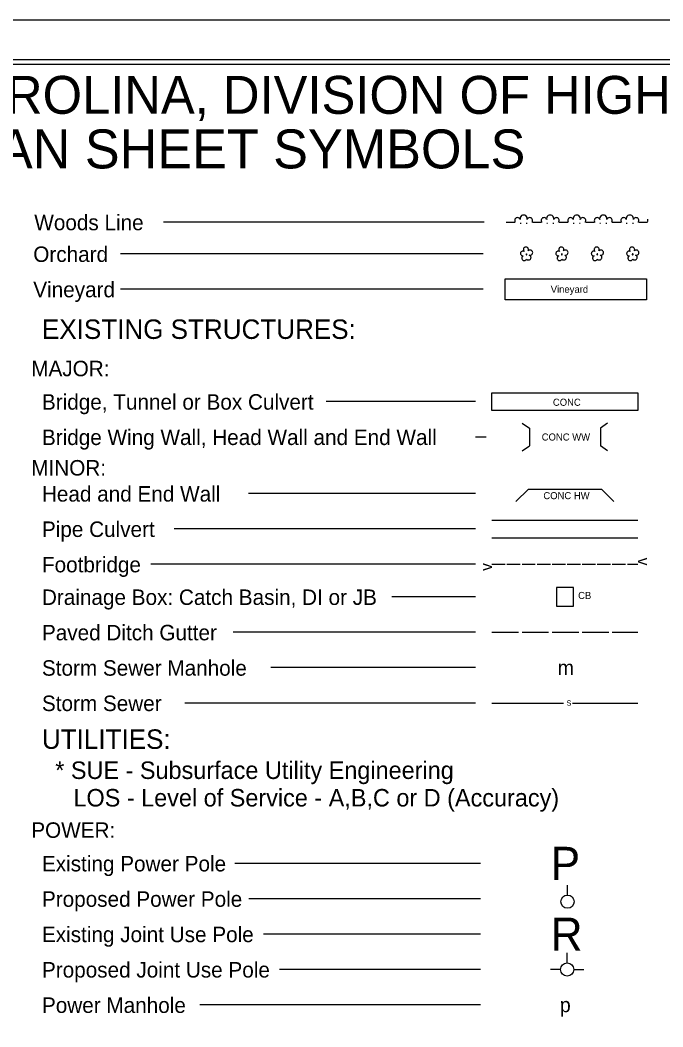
# Model space of a CAD drawing. Extents: x 1523758 to 1525442, y 311788 to 312888.
# Drawn here: x 1524681 to 1525044, y 312319 to 312888 of the extents above; entities that cross this region are included whole.
import ezdxf

# ---------------------------------------------------------------- set-up
doc = ezdxf.new("R2010")
doc.units = 0
for name, color, linetype in [('Sheet Cutting Line CELL', 7, 'Continuous'), ('Sheet Plot Border Inside CELL', 7, 'Continuous'), ('Sheet Plot Border Outside CELL', 7, 'Continuous'), ('Sheet Symbology CELL', 7, 'Continuous')]:
    doc.layers.add(name, color=color, linetype=linetype)

msp = doc.modelspace()

# ---------------------------------------------------------------- linework, layer by layer
at = {"layer": 'Sheet Cutting Line CELL'}
msp.add_line((1525442.07, 312888.39), (1523758.07, 312888.39), dxfattribs=at)
msp.add_line((1525442.07, 312888.39), (1523758.07, 312888.39), dxfattribs=at)
at = {"layer": 'Sheet Plot Border Inside CELL'}
msp.add_lwpolyline([(1523771.07, 311810.84), (1525437.57, 311810.84), (1525437.57, 312865.94), (1523771.07, 312865.94)], close=True, dxfattribs=at)
at = {"layer": 'Sheet Plot Border Outside CELL'}
msp.add_lwpolyline([(1523758.07, 311788.39), (1525442.07, 311788.39), (1525442.07, 312888.39), (1523758.07, 312888.39)], close=True, dxfattribs=at)
at = {"layer": 'Sheet Symbology CELL'}
for p, q in [((1524943.33, 312774.12), (1524762.21, 312774.12)), ((1524955.72, 312774.12), (1524960.72, 312774.12)), ((1524970.72, 312774.12), (1524975.72, 312774.12)), ((1524985.72, 312774.12), (1524990.72, 312774.12)), ((1525000.72, 312774.12), (1525005.72, 312774.12)), ((1525015.72, 312774.12), (1525020.72, 312774.12)), ((1525030.72, 312774.12), (1525035.72, 312774.12)), ((1524963.67, 312773.62), (1524964.17, 312773.62)), ((1524967.17, 312773.62), (1524967.67, 312773.62)), ((1524978.67, 312773.62), (1524979.17, 312773.62)), ((1524982.17, 312773.62), (1524982.67, 312773.62)), ((1524993.67, 312773.62), (1524994.17, 312773.62)), ((1524997.17, 312773.62), (1524997.67, 312773.62)), ((1525008.67, 312773.62), (1525009.17, 312773.62)), ((1525012.17, 312773.62), (1525012.67, 312773.62)), ((1525023.67, 312773.62), (1525024.17, 312773.62)), ((1525027.17, 312773.62), (1525027.67, 312773.62)), ((1524942.76, 312756.2), (1524737.83, 312756.2)), ((1524942.76, 312736.2), (1524737.83, 312736.2)), ((1524938.45, 312672.69), (1524854.02, 312672.69)), ((1524964.9, 312660.55), (1524969, 312657.69)), ((1525013.1, 312660.55), (1525009, 312657.69)), ((1524969, 312657.69), (1524969, 312647.69)), ((1525009, 312657.69), (1525009, 312647.69)), ((1524938.45, 312652.69), (1524944.44, 312652.69)), ((1524964.9, 312644.83), (1524969, 312647.69)), ((1525013.1, 312644.83), (1525009, 312647.69)), ((1524938.45, 312620.7), (1524810.15, 312620.7)), ((1524961.3, 312616.12), (1524968.37, 312623.2)), ((1524968.37, 312623.2), (1525009.62, 312623.2)), ((1525009.62, 312623.2), (1525016.7, 312616.12)), ((1524947.75, 312605.7), (1525030.25, 312605.7)), ((1524938.45, 312600.7), (1524768.26, 312600.7)), ((1524947.75, 312595.7), (1525030.25, 312595.7)), ((1524938.45, 312580.7), (1524754.97, 312580.7)), ((1524947.75, 312580.7), (1524955.25, 312580.7)), ((1524956.25, 312580.7), (1524963.75, 312580.7)), ((1524964.75, 312580.7), (1524972.25, 312580.7)), ((1524973.25, 312580.7), (1524980.75, 312580.7)), ((1524981.75, 312580.7), (1524989.25, 312580.7)), ((1524990.25, 312580.7), (1524997.75, 312580.7)), ((1524998.75, 312580.7), (1525006.25, 312580.7)), ((1525007.25, 312580.7), (1525014.75, 312580.7)), ((1525015.75, 312580.7), (1525023.25, 312580.7)), ((1525024.25, 312580.7), (1525030.25, 312580.7)), ((1524938.45, 312562.26), (1524891.25, 312562.26)), ((1524938.45, 312542.26), (1524801.5, 312542.26)), ((1524947.75, 312542.26), (1524962.75, 312542.26)), ((1524964.75, 312542.26), (1524979.75, 312542.26)), ((1524981.75, 312542.26), (1524996.75, 312542.26)), ((1524998.75, 312542.26), (1525013.75, 312542.26)), ((1525015.75, 312542.26), (1525030.25, 312542.26)), ((1524938.45, 312522.26), (1524822.77, 312522.26)), ((1524938.45, 312502.26), (1524774.25, 312502.26)), ((1524947.75, 312502.26), (1524988.27, 312502.26)), ((1524993.27, 312502.26), (1525030.25, 312502.26)), ((1524941.24, 312411.58), (1524802.54, 312411.58)), ((1524990.46, 312393.69), (1524990.46, 312399.32)), ((1524941.24, 312391.58), (1524810.32, 312391.58)), ((1524941.24, 312371.58), (1524818.72, 312371.58)), ((1524990.25, 312355.34), (1524990.25, 312360.97)), ((1524941.24, 312351.58), (1524827.72, 312351.58)), ((1524986.5, 312351.59), (1524980.87, 312351.59)), ((1524994, 312351.59), (1524999.62, 312351.59)), ((1524941.24, 312331.58), (1524782.74, 312331.58))]:
    msp.add_line(p, q, dxfattribs=at)
for points in [[(1525425.07, 312863.39), (1523925.07, 312863.39), (1523925.07, 311814.41), (1525425.07, 311814.41)], [(1524984.19, 312556.95), (1524993.8, 312556.95), (1524993.8, 312567.59), (1524984.19, 312567.59)]]:
    msp.add_lwpolyline(points, close=True, dxfattribs=at)
for points in [[(1524968.21, 312757.95), (1524968.36, 312758.25), (1524968.41, 312758.55), (1524968.36, 312758.85), (1524968.31, 312759.15), (1524968.16, 312759.4), (1524968.01, 312759.65), (1524967.76, 312759.85), (1524967.51, 312760), (1524967.16, 312760.1), (1524966.91, 312760.1), (1524966.61, 312760.05), (1524966.31, 312759.95), (1524966.06, 312759.8), (1524965.81, 312759.6), (1524965.66, 312759.3), (1524965.56, 312759.05), (1524965.51, 312758.75), (1524965.51, 312758.45), (1524965.56, 312758.15), (1524965.71, 312757.9), (1524965.91, 312757.6), (1524965.66, 312757.75), (1524965.36, 312757.8), (1524965.06, 312757.8), (1524964.81, 312757.7), (1524964.56, 312757.6), (1524964.31, 312757.4), (1524964.11, 312757.2), (1524963.96, 312756.95), (1524963.91, 312756.7), (1524963.86, 312756.35), (1524963.91, 312756.1), (1524964.01, 312755.85), (1524964.21, 312755.6), (1524964.36, 312755.4), (1524964.61, 312755.25), (1524964.91, 312755.1), (1524965.16, 312755.05), (1524965.46, 312755.05), (1524965.21, 312754.95), (1524964.96, 312754.75), (1524964.81, 312754.55), (1524964.71, 312754.25), (1524964.61, 312753.95), (1524964.61, 312753.7), (1524964.66, 312753.4), (1524964.81, 312753.15), (1524964.96, 312752.9), (1524965.16, 312752.7), (1524965.41, 312752.55), (1524965.66, 312752.45), (1524965.96, 312752.45), (1524966.26, 312752.45), (1524966.51, 312752.5), (1524966.76, 312752.7), (1524967.01, 312752.85), (1524967.26, 312753.3)], [(1524967.26, 312753.3), (1524967.86, 312752.95), (1524968.16, 312752.85), (1524968.46, 312752.8), (1524968.76, 312752.85), (1524969.01, 312752.95), (1524969.26, 312753.1), (1524969.51, 312753.3), (1524969.66, 312753.55), (1524969.76, 312753.8), (1524969.86, 312754.1), (1524969.81, 312754.4), (1524969.76, 312754.7), (1524969.56, 312755), (1524969.41, 312755.2), (1524969.16, 312755.35), (1524968.86, 312755.5), (1524969.16, 312755.45), (1524969.51, 312755.45), (1524969.76, 312755.55), (1524970.06, 312755.7), (1524970.31, 312755.85), (1524970.51, 312756.1), (1524970.66, 312756.4), (1524970.71, 312756.7), (1524970.76, 312757), (1524970.71, 312757.3), (1524970.61, 312757.6), (1524970.41, 312757.85), (1524970.16, 312758.1), (1524969.91, 312758.25), (1524969.61, 312758.35), (1524969.31, 312758.4), (1524969.01, 312758.4), (1524968.71, 312758.3), (1524968.46, 312758.15), (1524968.21, 312757.95)], [(1524988.21, 312757.95), (1524988.36, 312758.25), (1524988.41, 312758.55), (1524988.36, 312758.85), (1524988.31, 312759.15), (1524988.16, 312759.4), (1524988.01, 312759.65), (1524987.76, 312759.85), (1524987.51, 312760), (1524987.16, 312760.1), (1524986.91, 312760.1), (1524986.61, 312760.05), (1524986.31, 312759.95), (1524986.06, 312759.8), (1524985.81, 312759.6), (1524985.66, 312759.3), (1524985.56, 312759.05), (1524985.51, 312758.75), (1524985.51, 312758.45), (1524985.56, 312758.15), (1524985.71, 312757.9), (1524985.91, 312757.6), (1524985.66, 312757.75), (1524985.36, 312757.8), (1524985.06, 312757.8), (1524984.81, 312757.7), (1524984.56, 312757.6), (1524984.31, 312757.4), (1524984.11, 312757.2), (1524983.96, 312756.95), (1524983.91, 312756.7), (1524983.86, 312756.35), (1524983.91, 312756.1), (1524984.01, 312755.85), (1524984.21, 312755.6), (1524984.36, 312755.4), (1524984.61, 312755.25), (1524984.91, 312755.1), (1524985.16, 312755.05), (1524985.46, 312755.05), (1524985.21, 312754.95), (1524984.96, 312754.75), (1524984.81, 312754.55), (1524984.71, 312754.25), (1524984.61, 312753.95), (1524984.61, 312753.7), (1524984.66, 312753.4), (1524984.81, 312753.15), (1524984.96, 312752.9), (1524985.16, 312752.7), (1524985.41, 312752.55), (1524985.66, 312752.45), (1524985.96, 312752.45), (1524986.26, 312752.45), (1524986.51, 312752.5), (1524986.76, 312752.7), (1524987.01, 312752.85), (1524987.26, 312753.3)], [(1524987.26, 312753.3), (1524987.86, 312752.95), (1524988.16, 312752.85), (1524988.46, 312752.8), (1524988.76, 312752.85), (1524989.01, 312752.95), (1524989.26, 312753.1), (1524989.51, 312753.3), (1524989.66, 312753.55), (1524989.76, 312753.8), (1524989.86, 312754.1), (1524989.81, 312754.4), (1524989.76, 312754.7), (1524989.56, 312755), (1524989.41, 312755.2), (1524989.16, 312755.35), (1524988.86, 312755.5), (1524989.16, 312755.45), (1524989.51, 312755.45), (1524989.76, 312755.55), (1524990.06, 312755.7), (1524990.31, 312755.85), (1524990.51, 312756.1), (1524990.66, 312756.4), (1524990.71, 312756.7), (1524990.76, 312757), (1524990.71, 312757.3), (1524990.61, 312757.6), (1524990.41, 312757.85), (1524990.16, 312758.1), (1524989.91, 312758.25), (1524989.61, 312758.35), (1524989.31, 312758.4), (1524989.01, 312758.4), (1524988.71, 312758.3), (1524988.46, 312758.15), (1524988.21, 312757.95)], [(1525008.21, 312757.95), (1525008.36, 312758.25), (1525008.41, 312758.55), (1525008.36, 312758.85), (1525008.31, 312759.15), (1525008.16, 312759.4), (1525008.01, 312759.65), (1525007.76, 312759.85), (1525007.51, 312760), (1525007.16, 312760.1), (1525006.91, 312760.1), (1525006.61, 312760.05), (1525006.31, 312759.95), (1525006.06, 312759.8), (1525005.81, 312759.6), (1525005.66, 312759.3), (1525005.56, 312759.05), (1525005.51, 312758.75), (1525005.51, 312758.45), (1525005.56, 312758.15), (1525005.71, 312757.9), (1525005.91, 312757.6), (1525005.66, 312757.75), (1525005.36, 312757.8), (1525005.06, 312757.8), (1525004.81, 312757.7), (1525004.56, 312757.6), (1525004.31, 312757.4), (1525004.11, 312757.2), (1525003.96, 312756.95), (1525003.91, 312756.7), (1525003.86, 312756.35), (1525003.91, 312756.1), (1525004.01, 312755.85), (1525004.21, 312755.6), (1525004.36, 312755.4), (1525004.61, 312755.25), (1525004.91, 312755.1), (1525005.16, 312755.05), (1525005.46, 312755.05), (1525005.21, 312754.95), (1525004.96, 312754.75), (1525004.81, 312754.55), (1525004.71, 312754.25), (1525004.61, 312753.95), (1525004.61, 312753.7), (1525004.66, 312753.4), (1525004.81, 312753.15), (1525004.96, 312752.9), (1525005.16, 312752.7), (1525005.41, 312752.55), (1525005.66, 312752.45), (1525005.96, 312752.45), (1525006.26, 312752.45), (1525006.51, 312752.5), (1525006.76, 312752.7), (1525007.01, 312752.85), (1525007.26, 312753.3)], [(1525007.26, 312753.3), (1525007.86, 312752.95), (1525008.16, 312752.85), (1525008.46, 312752.8), (1525008.76, 312752.85), (1525009.01, 312752.95), (1525009.26, 312753.1), (1525009.51, 312753.3), (1525009.66, 312753.55), (1525009.76, 312753.8), (1525009.86, 312754.1), (1525009.81, 312754.4), (1525009.76, 312754.7), (1525009.56, 312755), (1525009.41, 312755.2), (1525009.16, 312755.35), (1525008.86, 312755.5), (1525009.16, 312755.45), (1525009.51, 312755.45), (1525009.76, 312755.55), (1525010.06, 312755.7), (1525010.31, 312755.85), (1525010.51, 312756.1), (1525010.66, 312756.4), (1525010.71, 312756.7), (1525010.76, 312757), (1525010.71, 312757.3), (1525010.61, 312757.6), (1525010.41, 312757.85), (1525010.16, 312758.1), (1525009.91, 312758.25), (1525009.61, 312758.35), (1525009.31, 312758.4), (1525009.01, 312758.4), (1525008.71, 312758.3), (1525008.46, 312758.15), (1525008.21, 312757.95)], [(1525028.21, 312757.95), (1525028.36, 312758.25), (1525028.41, 312758.55), (1525028.36, 312758.85), (1525028.31, 312759.15), (1525028.16, 312759.4), (1525028.01, 312759.65), (1525027.76, 312759.85), (1525027.51, 312760), (1525027.16, 312760.1), (1525026.91, 312760.1), (1525026.61, 312760.05), (1525026.31, 312759.95), (1525026.06, 312759.8), (1525025.81, 312759.6), (1525025.66, 312759.3), (1525025.56, 312759.05), (1525025.51, 312758.75), (1525025.51, 312758.45), (1525025.56, 312758.15), (1525025.71, 312757.9), (1525025.91, 312757.6), (1525025.66, 312757.75), (1525025.36, 312757.8), (1525025.06, 312757.8), (1525024.81, 312757.7), (1525024.56, 312757.6), (1525024.31, 312757.4), (1525024.11, 312757.2), (1525023.96, 312756.95), (1525023.91, 312756.7), (1525023.86, 312756.35), (1525023.91, 312756.1), (1525024.01, 312755.85), (1525024.21, 312755.6), (1525024.36, 312755.4), (1525024.61, 312755.25), (1525024.91, 312755.1), (1525025.16, 312755.05), (1525025.46, 312755.05), (1525025.21, 312754.95), (1525024.96, 312754.75), (1525024.81, 312754.55), (1525024.71, 312754.25), (1525024.61, 312753.95), (1525024.61, 312753.7), (1525024.66, 312753.4), (1525024.81, 312753.15), (1525024.96, 312752.9), (1525025.16, 312752.7), (1525025.41, 312752.55), (1525025.66, 312752.45), (1525025.96, 312752.45), (1525026.26, 312752.45), (1525026.51, 312752.5), (1525026.76, 312752.7), (1525027.01, 312752.85), (1525027.26, 312753.3)], [(1525027.26, 312753.3), (1525027.86, 312752.95), (1525028.16, 312752.85), (1525028.46, 312752.8), (1525028.76, 312752.85), (1525029.01, 312752.95), (1525029.26, 312753.1), (1525029.51, 312753.3), (1525029.66, 312753.55), (1525029.76, 312753.8), (1525029.86, 312754.1), (1525029.81, 312754.4), (1525029.76, 312754.7), (1525029.56, 312755), (1525029.41, 312755.2), (1525029.16, 312755.35), (1525028.86, 312755.5), (1525029.16, 312755.45), (1525029.51, 312755.45), (1525029.76, 312755.55), (1525030.06, 312755.7), (1525030.31, 312755.85), (1525030.51, 312756.1), (1525030.66, 312756.4), (1525030.71, 312756.7), (1525030.76, 312757), (1525030.71, 312757.3), (1525030.61, 312757.6), (1525030.41, 312757.85), (1525030.16, 312758.1), (1525029.91, 312758.25), (1525029.61, 312758.35), (1525029.31, 312758.4), (1525029.01, 312758.4), (1525028.71, 312758.3), (1525028.46, 312758.15), (1525028.21, 312757.95)], [(1524967.36, 312756.2), (1524967.21, 312756.2), (1524967.11, 312756.15), (1524967.01, 312756.1), (1524967.01, 312755.95), (1524967.01, 312755.85), (1524967.11, 312755.75), (1524967.26, 312755.75), (1524967.36, 312755.75), (1524967.46, 312755.85), (1524967.51, 312756), (1524967.46, 312756.1), (1524967.36, 312756.2)], [(1524987.36, 312756.2), (1524987.21, 312756.2), (1524987.11, 312756.15), (1524987.01, 312756.1), (1524987.01, 312755.95), (1524987.01, 312755.85), (1524987.11, 312755.75), (1524987.26, 312755.75), (1524987.36, 312755.75), (1524987.46, 312755.85), (1524987.51, 312756), (1524987.46, 312756.1), (1524987.36, 312756.2)], [(1525007.36, 312756.2), (1525007.21, 312756.2), (1525007.11, 312756.15), (1525007.01, 312756.1), (1525007.01, 312755.95), (1525007.01, 312755.85), (1525007.11, 312755.75), (1525007.26, 312755.75), (1525007.36, 312755.75), (1525007.46, 312755.85), (1525007.51, 312756), (1525007.46, 312756.1), (1525007.36, 312756.2)], [(1525027.36, 312756.2), (1525027.21, 312756.2), (1525027.11, 312756.15), (1525027.01, 312756.1), (1525027.01, 312755.95), (1525027.01, 312755.85), (1525027.11, 312755.75), (1525027.26, 312755.75), (1525027.36, 312755.75), (1525027.46, 312755.85), (1525027.51, 312756), (1525027.46, 312756.1), (1525027.36, 312756.2)], [(1524955.16, 312742.2), (1525035.16, 312742.2), (1525035.16, 312730.2), (1524955.16, 312730.2), (1524955.16, 312742.2)], [(1524947.75, 312677.69), (1525030.25, 312677.69), (1525030.25, 312667.69), (1524947.75, 312667.69), (1524947.75, 312677.69)]]:
    msp.add_lwpolyline(points, dxfattribs=at)
for centre in [(1524990.46, 312389.94), (1524990.25, 312351.58)]:
    msp.add_circle(centre, 3.75, dxfattribs=at)
for centre, radius, start, end in [((1524962.17, 312775.14), 1.58, 18.435, 219.2315), ((1524965.67, 312776.14), 2.06, 345.9638, 194.0362), ((1524969.17, 312775.14), 1.58, 320.7685, 161.5651), ((1524977.17, 312775.14), 1.58, 18.435, 219.2315), ((1524980.67, 312776.14), 2.06, 345.9638, 194.0362), ((1524984.17, 312775.14), 1.58, 320.7685, 161.5651), ((1524992.17, 312775.14), 1.58, 18.435, 219.2315), ((1524995.67, 312776.14), 2.06, 345.9638, 194.0362), ((1524999.17, 312775.14), 1.58, 320.7685, 161.5651), ((1525007.17, 312775.14), 1.58, 18.435, 219.2315), ((1525010.67, 312776.14), 2.06, 345.9638, 194.0362), ((1525014.17, 312775.14), 1.58, 320.7685, 161.5651), ((1525022.17, 312775.14), 1.58, 18.435, 219.2315), ((1525025.67, 312776.14), 2.06, 345.9638, 194.0362), ((1525029.17, 312775.14), 1.58, 320.7685, 161.5651), ((1525037.17, 312775.14), 1.58, 156.251, 203.749)]:
    msp.add_arc(centre, radius, start, end, dxfattribs=at)

# ---------------------------------------------------------------- texts
for s, height, p in [('STATE OF NORTH CAROLINA, DIVISION OF HIGHWAYS', 21.419, (1524375.63, 312835.43)), ('CONVENTIONAL  PLAN SHEET SYMBOLS', 22.0323, (1524383.76, 312804.55)), ('Woods Line', 8.75, (1524689.17, 312769.6)), ('Orchard', 8.75, (1524688.6, 312751.67)), ('Vineyard', 8.75, (1524688.6, 312731.67)), ('EXISTING STRUCTURES:', 11, (1524693.49, 312708.14)), ('MAJOR:', 8.75, (1524687.46, 312687.03)), ('Bridge, Tunnel or Box Culvert', 8.75, (1524693.49, 312668.14)), ('CONC', 4, (1524982.19, 312670.33)), ('Bridge Wing Wall, Head Wall and End Wall', 8.75, (1524693.49, 312648.14)), ('MINOR:', 8.75, (1524687.46, 312630.9)), ('Head and End Wall', 8.75, (1524693.49, 312616.15)), ('Pipe Culvert', 8.75, (1524693.49, 312596.16)), ('Footbridge', 8.75, (1524693.5, 312576.16)), ('Drainage Box: Catch Basin, DI or JB', 8.75, (1524693.5, 312557.72)), ('Paved Ditch Gutter', 8.75, (1524693.5, 312537.71)), ('Storm Sewer Manhole', 8.75, (1524693.5, 312517.71)), ('m', 8.25, (1524984.87, 312518.14)), ('Storm Sewer', 8.75, (1524693.5, 312497.71)), ('S', 3, (1524989.87, 312500.76)), ('UTILITIES:', 11, (1524693.49, 312476.35)), ('POWER:', 8.75, (1524687.46, 312426.04)), ('P', 18.75, (1524980.87, 312402.2)), ('Existing Power Pole', 8.75, (1524693.5, 312407.04)), ('Proposed Power Pole', 8.75, (1524693.5, 312387.04)), ('Existing Joint Use Pole', 8.75, (1524693.5, 312367.05)), ('R', 18.75, (1524980.87, 312362.2)), ('Proposed Joint Use Pole', 8.75, (1524693.51, 312347.04)), ('Power Manhole', 8.75, (1524693.51, 312327.04)), ('p', 8.25, (1524986.12, 312327.45))]:
    msp.add_text(s, height=height, dxfattribs=at).set_placement(p)
for s, height, rotation, p in [('Vineyard', 4, 0, (1524980.98, 312734.2)), ('CONC WW', 4, 0, (1524975.87, 312650.69)), ('CONC HW', 4, 360, (1524976.8, 312617.53)), ('v', 6.6, 89.7591, (1524947.74, 312576.96)), ('v', 6.6, 270.2409, (1525030.24, 312584.43)), ('CB', 4, 360, (1524996.44, 312561.09)), ('* SUE - Subsurface Utility Engineering', 9.9, 360, (1524701.02, 312459.32)), ('LOS - Level of Service - A,B,C or D (Accuracy) ', 9.9, 360, (1524711.29, 312443.76))]:
    msp.add_text(s, height=height, rotation=rotation, dxfattribs=at).set_placement(p)

doc.saveas('drawing.dxf')
